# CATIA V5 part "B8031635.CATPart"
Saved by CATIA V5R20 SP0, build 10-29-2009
Part number: B8031635
Revision: 7
Definition: design
Nomenclature: B8031635
Source: made
Description: NOT SPECIFIED
Bounding box of the stored display mesh (mm): x -14 to 14, y -14 to 14, z 0 to 35
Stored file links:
  C:\Users\Utente\Desktop\3D files B803\B8031635.CATPart
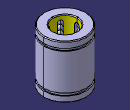
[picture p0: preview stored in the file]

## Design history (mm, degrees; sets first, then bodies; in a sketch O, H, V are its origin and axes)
Body1 "MANIFOLD_SOLID_BREP #38" (main body)
  Solid1: solid without history
Body2 "MANIFOLD_SOLID_BREP #76"
  Solid2: solid without history
Body3 "MANIFOLD_SOLID_BREP #114"
  Solid3: solid without history
Body4 "MANIFOLD_SOLID_BREP #152"
  Solid4: solid without history
Body5 "MANIFOLD_SOLID_BREP #190"
  Solid5: solid without history
Body6 "MANIFOLD_SOLID_BREP #228"
  Solid6: solid without history
Body7 "MANIFOLD_SOLID_BREP #266"
  Solid7: solid without history
Body8 "MANIFOLD_SOLID_BREP #304"
  Solid8: solid without history
Body9 "MANIFOLD_SOLID_BREP #2066"
  Solid9: solid without history
Body10 "MANIFOLD_SOLID_BREP #2104"
  Solid10: solid without history
Body11 "MANIFOLD_SOLID_BREP #2142"
  Solid11: solid without history
Body12 "MANIFOLD_SOLID_BREP #2180"
  Solid12: solid without history
Body13 "MANIFOLD_SOLID_BREP #2218"
  Solid13: solid without history
Body14 "MANIFOLD_SOLID_BREP #2256"
  Solid14: solid without history
Body15 "MANIFOLD_SOLID_BREP #2294"
  Solid15: solid without history
Body16 "MANIFOLD_SOLID_BREP #2332"
  Solid16: solid without history
Body17 "MANIFOLD_SOLID_BREP #2370"
  Solid17: solid without history
Body18 "MANIFOLD_SOLID_BREP #2408"
  Solid18: solid without history
Body19 "MANIFOLD_SOLID_BREP #2446"
  Solid19: solid without history
Body20 "MANIFOLD_SOLID_BREP #2484"
  Solid20: solid without history
Body21 "MANIFOLD_SOLID_BREP #2522"
  Solid21: solid without history
Body22 "MANIFOLD_SOLID_BREP #2560"
  Solid22: solid without history
Body23 "MANIFOLD_SOLID_BREP #2598"
  Solid23: solid without history
Body24 "MANIFOLD_SOLID_BREP #2636"
  Solid24: solid without history
Body25 "MANIFOLD_SOLID_BREP #2674"
  Solid25: solid without history
Body26 "MANIFOLD_SOLID_BREP #2712"
  Solid26: solid without history
Body27 "MANIFOLD_SOLID_BREP #2750"
  Solid27: solid without history
Body28 "MANIFOLD_SOLID_BREP #2788"
  Solid28: solid without history
Body29 "MANIFOLD_SOLID_BREP #2826"
  Solid29: solid without history
Body30 "MANIFOLD_SOLID_BREP #2864"
  Solid30: solid without history
Body31 "MANIFOLD_SOLID_BREP #2902"
  Solid31: solid without history
Body32 "MANIFOLD_SOLID_BREP #2940"
  Solid32: solid without history
Body33 "MANIFOLD_SOLID_BREP #2978"
  Solid33: solid without history
Body34 "MANIFOLD_SOLID_BREP #3016"
  Solid34: solid without history
Body35 "MANIFOLD_SOLID_BREP #3054"
  Solid35: solid without history
Body36 "MANIFOLD_SOLID_BREP #3092"
  Solid36: solid without history
Body37 "MANIFOLD_SOLID_BREP #3130"
  Solid37: solid without history
Body38 "MANIFOLD_SOLID_BREP #3168"
  Solid38: solid without history
Body39 "MANIFOLD_SOLID_BREP #3206"
  Solid39: solid without history
Body40 "MANIFOLD_SOLID_BREP #3244"
  Solid40: solid without history
Body41 "MANIFOLD_SOLID_BREP #3282"
  Solid41: solid without history
Body42 "MANIFOLD_SOLID_BREP #3320"
  Solid42: solid without history
Body43 "MANIFOLD_SOLID_BREP #3358"
  Solid43: solid without history
Body44 "MANIFOLD_SOLID_BREP #3396"
  Solid44: solid without history
Body45 "MANIFOLD_SOLID_BREP #3434"
  Solid45: solid without history
Body46 "MANIFOLD_SOLID_BREP #3472"
  Solid46: solid without history
Body47 "MANIFOLD_SOLID_BREP #3510"
  Solid47: solid without history
Body48 "MANIFOLD_SOLID_BREP #3548"
  Solid48: solid without history
Body49 "MANIFOLD_SOLID_BREP #3586"
  Solid49: solid without history
Body50 "MANIFOLD_SOLID_BREP #3624"
  Solid50: solid without history
Body51 "MANIFOLD_SOLID_BREP #3662"
  Solid51: solid without history
Body52 "MANIFOLD_SOLID_BREP #3700"
  Solid52: solid without history
Body53 "MANIFOLD_SOLID_BREP #3738"
  Solid53: solid without history
Body54 "MANIFOLD_SOLID_BREP #3776"
  Solid54: solid without history
Body55 "MANIFOLD_SOLID_BREP #3814"
  Solid55: solid without history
